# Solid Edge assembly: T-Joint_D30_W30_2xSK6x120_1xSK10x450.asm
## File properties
Author: fknapp
Template: iso metric assembly.asm
Last saved by: fknapp
Revision: 11
Application: Solid Edge
Username: fknapp
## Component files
T-Joint_D30_W30.par
SK Schraube 6x120_ohne_Gewinde.par
SK Schraube 10x450_ohne_Gewinde_22042020.par
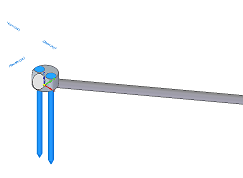
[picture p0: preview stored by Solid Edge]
